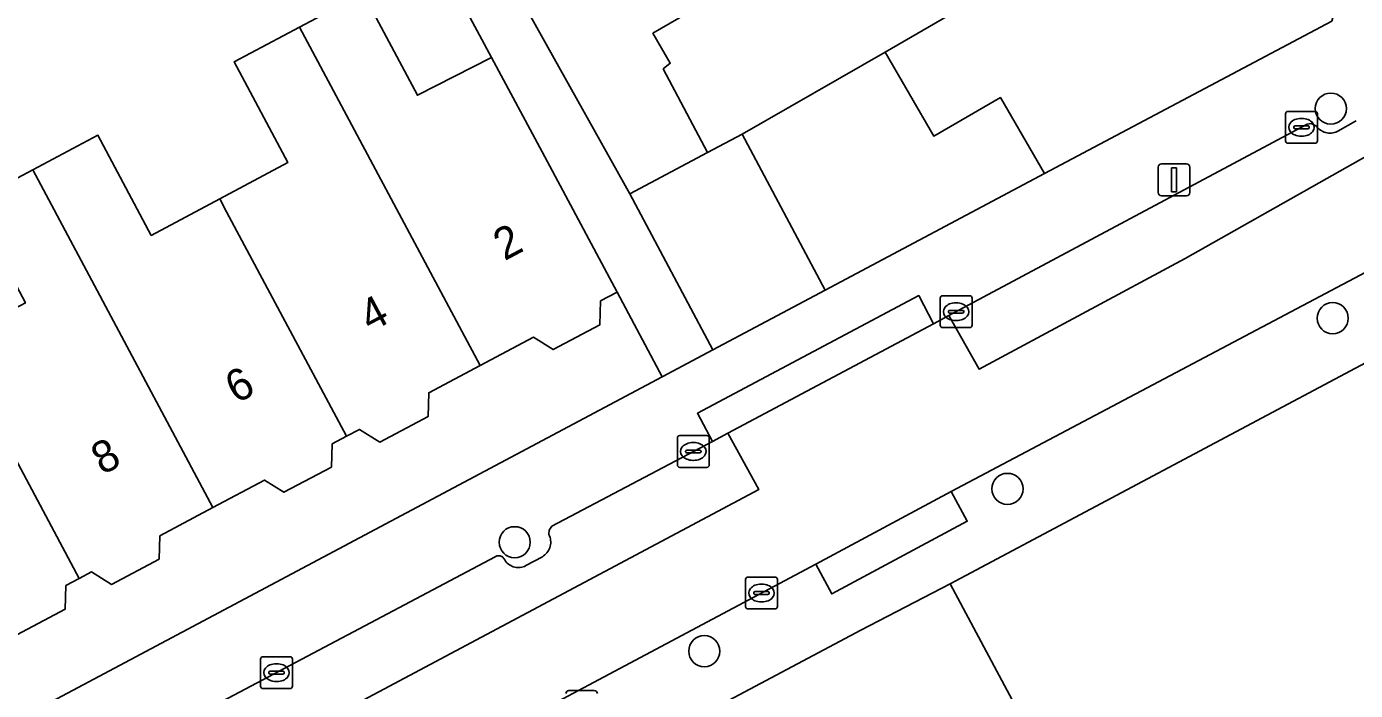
# Model space of a CAD drawing. Extents: x 160304 to 160955, y 383684 to 384161.
# Drawn here: x 160717.68 to 160759.4, y 383943.28 to 383964.14 of the extents above; entities that cross this region are included whole.
import ezdxf

# ---------------------------------------------------------------- set-up
doc = ezdxf.new("R2010")
doc.units = 0
for name, color, linetype in [('IMGEO_Boom', 7, 'Continuous'), ('IMGEO_Erf', 7, 'Continuous'), ('IMGEO_Kolk', 7, 'Continuous'), ('IMGEO_Lichtmast', 7, 'Continuous'), ('IMGEO_Muur', 7, 'Continuous'), ('IMGEO_Pand', 7, 'Continuous'), ('IMGEO_Pand_nummerreeks', 7, 'Continuous'), ('IMGEO_Parkeervlak_open', 7, 'Continuous'), ('IMGEO_Rijbaan_lokaal_open', 7, 'Continuous'), ('IMGEO_Voetpad_open', 7, 'Continuous')]:
    doc.layers.add(name, color=color, linetype=linetype)

msp = doc.modelspace()

# ---------------------------------------------------------------- linework, layer by layer
at = {"layer": 'IMGEO_Boom'}
for centre in [(160758.629, 383961.564), (160758.689, 383954.978), (160748.476, 383949.614), (160733.003, 383947.938), (160738.956, 383944.513)]:
    msp.add_circle(centre, 0.489, dxfattribs=at)
at = {"layer": 'IMGEO_Erf'}
for points in [[(160736.798, 383976.222), (160738.684, 383977.316), (160737.689, 383979.03), (160740.352, 383980.577), (160738.846, 383983.173), (160734.749, 383980.796), (160733.069, 383983.69), (160732.736, 383983.497), (160730.765, 383986.894), (160723.262, 383982.797), (160723.802, 383981.83), (160728.293, 383973.789), (160736.616, 383958.886), (160739.062, 383960.187), (160737.667, 383962.81), (160737.889, 383962.992), (160737.344, 383963.932), (160742.852, 383967.128), (160743.413, 383966.161), (160747.485, 383968.507), (160746.079, 383970.931), (160744.693, 383973.319), (160740.047, 383970.623), (160738.585, 383973.143)], [(160742.754, 383955.863), (160749.64, 383959.525), (160748.256, 383961.913), (160746.163, 383960.699), (160744.633, 383963.338), (160740.148, 383960.764)]]:
    msp.add_lwpolyline(points, close=True, dxfattribs=at)
for points in [[(160715.957, 383958.62), (160717.868, 383959.637), (160719.915, 383960.727), (160721.589, 383957.582), (160723.741, 383958.728), (160725.879, 383959.866), (160724.193, 383963.034), (160726.249, 383964.129), (160728.244, 383965.191), (160729.95, 383961.985), (160732.277, 383963.17), (160725.597, 383975.619)], [(160678.654, 383921.738), (160737.631, 383953.138), (160736.216, 383955.795), (160735.698, 383955.519), (160735.673, 383954.765), (160734.215, 383953.99), (160733.589, 383954.381), (160731.921, 383953.493), (160730.306, 383952.634), (160730.281, 383951.889), (160728.766, 383951.083), (160728.125, 383951.484), (160727.72, 383951.268), (160727.271, 383951.029), (160727.246, 383950.301), (160725.757, 383949.509), (160725.149, 383949.889), (160723.527, 383949.025), (160721.863, 383948.139), (160721.838, 383947.407), (160720.346, 383946.613), (160719.716, 383947.006), (160719.327, 383946.799), (160718.907, 383946.575), (160718.882, 383945.833), (160717.372, 383945.03)], [(160749.029, 383942.219), (160746.679, 383946.631), (160743.868, 383945.177), (160733.256, 383939.529)]]:
    msp.add_lwpolyline(points, dxfattribs=at)
at = {"layer": 'IMGEO_Kolk'}
for p, q in [((160757.208, 383960.551), (160757.208, 383961.403)), ((160757.283, 383961.477), (160758.135, 383961.477)), ((160757.696, 383961.257), (160757.721, 383961.257)), ((160758.209, 383961.403), (160758.209, 383960.551)), ((160757.467, 383960.971), (160757.467, 383960.983)), ((160757.905, 383960.934), (160757.507, 383960.934)), ((160757.51, 383961.02), (160757.908, 383961.02)), ((160757.719, 383960.697), (160757.694, 383960.697)), ((160757.951, 383960.983), (160757.951, 383960.971)), ((160758.135, 383960.477), (160757.283, 383960.477)), ((160746.438, 383955.682), (160747.29, 383955.682)), ((160746.363, 383954.756), (160746.363, 383955.608)), ((160746.851, 383955.462), (160746.876, 383955.462)), ((160747.364, 383955.608), (160747.364, 383954.756)), ((160746.622, 383955.176), (160746.622, 383955.188)), ((160747.06, 383955.139), (160746.662, 383955.139)), ((160746.665, 383955.225), (160747.063, 383955.225)), ((160746.874, 383954.902), (160746.849, 383954.902)), ((160747.106, 383955.188), (160747.106, 383955.176)), ((160747.29, 383954.682), (160746.438, 383954.682)), ((160738.111, 383950.365), (160738.111, 383951.217)), ((160738.186, 383951.291), (160739.038, 383951.291)), ((160738.599, 383951.071), (160738.624, 383951.071)), ((160739.112, 383951.217), (160739.112, 383950.365)), ((160738.37, 383950.785), (160738.37, 383950.797)), ((160738.808, 383950.748), (160738.41, 383950.748)), ((160738.413, 383950.834), (160738.811, 383950.834)), ((160738.854, 383950.797), (160738.854, 383950.785)), ((160739.038, 383950.291), (160738.186, 383950.291)), ((160738.622, 383950.511), (160738.597, 383950.511)), ((160740.253, 383945.916), (160740.253, 383946.768)), ((160740.328, 383946.842), (160741.18, 383946.842)), ((160740.741, 383946.622), (160740.766, 383946.622)), ((160741.254, 383946.768), (160741.254, 383945.916)), ((160740.512, 383946.336), (160740.512, 383946.348)), ((160740.95, 383946.299), (160740.552, 383946.299)), ((160740.555, 383946.385), (160740.953, 383946.385)), ((160740.996, 383946.348), (160740.996, 383946.336)), ((160741.18, 383945.842), (160740.328, 383945.842)), ((160740.764, 383946.062), (160740.739, 383946.062)), ((160725.023, 383943.414), (160725.023, 383944.266)), ((160725.098, 383944.34), (160725.95, 383944.34)), ((160725.511, 383944.12), (160725.536, 383944.12)), ((160726.024, 383944.266), (160726.024, 383943.414)), ((160725.282, 383943.834), (160725.282, 383943.846)), ((160725.72, 383943.797), (160725.322, 383943.797)), ((160725.325, 383943.883), (160725.723, 383943.883)), ((160725.534, 383943.56), (160725.509, 383943.56)), ((160725.766, 383943.846), (160725.766, 383943.834)), ((160725.95, 383943.34), (160725.098, 383943.34))]:
    msp.add_line(p, q, dxfattribs=at)
for points in [[(160757.208, 383960.551), (160757.208, 383961.403)], [(160757.283, 383961.477), (160758.135, 383961.477)], [(160758.209, 383961.403), (160758.209, 383960.551)], [(160758.135, 383960.477), (160757.283, 383960.477)], [(160746.438, 383955.682), (160747.29, 383955.682)], [(160746.363, 383954.756), (160746.363, 383955.608)], [(160747.364, 383955.608), (160747.364, 383954.756)], [(160747.29, 383954.682), (160746.438, 383954.682)], [(160738.111, 383950.365), (160738.111, 383951.217)], [(160738.186, 383951.291), (160739.038, 383951.291)], [(160739.112, 383951.217), (160739.112, 383950.365)], [(160739.038, 383950.291), (160738.186, 383950.291)], [(160740.253, 383945.916), (160740.253, 383946.768)], [(160740.328, 383946.842), (160741.18, 383946.842)], [(160741.254, 383946.768), (160741.254, 383945.916)], [(160741.18, 383945.842), (160740.328, 383945.842)], [(160725.023, 383943.414), (160725.023, 383944.266)], [(160725.098, 383944.34), (160725.95, 383944.34)], [(160726.024, 383944.266), (160726.024, 383943.414)], [(160725.95, 383943.34), (160725.098, 383943.34)]]:
    msp.add_lwpolyline(points, dxfattribs=at)
for centre, radius, start, end in [((160757.285, 383961.401), 0.0765, 91.552, 178.448), ((160757.285, 383961.401), 0.0765, 91.552, 178.448), ((160758.133, 383961.401), 0.0765, 1.552, 88.448), ((160758.133, 383961.401), 0.0765, 1.552, 88.448), ((160757.507, 383960.98), 0.0403, 85.8775, 175.7526), ((160757.504, 383960.97), 0.0366, 178.938, 274.7102), ((160757.908, 383960.977), 0.043, 264.8664, 352.4533), ((160757.912, 383960.982), 0.0386, 1.7309, 96.639), ((160757.285, 383960.553), 0.0765, 181.552, 268.448), ((160757.285, 383960.553), 0.0765, 181.552, 268.448), ((160758.133, 383960.553), 0.0765, 271.552, 358.448), ((160758.133, 383960.553), 0.0765, 271.552, 358.448), ((160746.44, 383955.606), 0.0765, 91.552, 178.448), ((160746.44, 383955.606), 0.0765, 91.552, 178.448), ((160747.288, 383955.606), 0.0765, 1.552, 88.448), ((160747.288, 383955.606), 0.0765, 1.552, 88.448), ((160746.662, 383955.185), 0.0403, 85.8775, 175.7526), ((160746.659, 383955.175), 0.0366, 178.938, 274.7102), ((160747.063, 383955.182), 0.043, 264.8664, 352.4533), ((160747.067, 383955.187), 0.0386, 1.7309, 96.639), ((160746.44, 383954.758), 0.0765, 181.552, 268.448), ((160746.44, 383954.758), 0.0765, 181.552, 268.448), ((160747.288, 383954.758), 0.0765, 271.552, 358.448), ((160747.288, 383954.758), 0.0765, 271.552, 358.448), ((160738.188, 383951.215), 0.0765, 91.552, 178.448), ((160738.188, 383951.215), 0.0765, 91.552, 178.448), ((160739.036, 383951.215), 0.0765, 1.552, 88.448), ((160739.036, 383951.215), 0.0765, 1.552, 88.448), ((160738.41, 383950.794), 0.0403, 85.8775, 175.7526), ((160738.407, 383950.784), 0.0366, 178.938, 274.7102), ((160738.811, 383950.791), 0.043, 264.8664, 352.4533), ((160738.815, 383950.796), 0.0386, 1.7309, 96.639), ((160738.188, 383950.367), 0.0765, 181.552, 268.448), ((160738.188, 383950.367), 0.0765, 181.552, 268.448), ((160739.036, 383950.367), 0.0765, 271.552, 358.448), ((160739.036, 383950.367), 0.0765, 271.552, 358.448), ((160740.33, 383946.766), 0.0765, 91.552, 178.448), ((160740.33, 383946.766), 0.0765, 91.552, 178.448), ((160741.178, 383946.766), 0.0765, 1.552, 88.448), ((160741.178, 383946.766), 0.0765, 1.552, 88.448), ((160740.552, 383946.345), 0.0403, 85.8775, 175.7526), ((160740.549, 383946.335), 0.0366, 178.938, 274.7102), ((160740.953, 383946.342), 0.043, 264.8664, 352.4533), ((160740.957, 383946.347), 0.0386, 1.7309, 96.639), ((160740.33, 383945.918), 0.0765, 181.552, 268.448), ((160740.33, 383945.918), 0.0765, 181.552, 268.448), ((160741.178, 383945.918), 0.0765, 271.552, 358.448), ((160741.178, 383945.918), 0.0765, 271.552, 358.448), ((160725.1, 383944.264), 0.0765, 91.552, 178.448), ((160725.1, 383944.264), 0.0765, 91.552, 178.448), ((160725.948, 383944.264), 0.0765, 1.552, 88.448), ((160725.948, 383944.264), 0.0765, 1.552, 88.448), ((160725.322, 383943.843), 0.0403, 85.8775, 175.7526), ((160725.319, 383943.833), 0.0366, 178.938, 274.7102), ((160725.723, 383943.84), 0.043, 264.8664, 352.4533), ((160725.727, 383943.845), 0.0386, 1.7309, 96.639), ((160725.1, 383943.416), 0.0765, 181.552, 268.448), ((160725.1, 383943.416), 0.0765, 181.552, 268.448), ((160725.948, 383943.416), 0.0765, 271.552, 358.448), ((160725.948, 383943.416), 0.0765, 271.552, 358.448)]:
    msp.add_arc(centre, radius, start, end, dxfattribs=at)
for centre, major_axis, ratio, start_param, end_param in [((160757.695, 383960.977), (-0.387, 0.002), 0.722429, 4.712389, 7.853982), ((160757.72, 383960.977), (-0.39, 0.002), 0.717154, 1.570796, 4.712389), ((160746.85, 383955.182), (-0.387, 0.002), 0.722429, 4.712389, 7.853982), ((160746.875, 383955.182), (-0.39, 0.002), 0.717154, 1.570796, 4.712389), ((160738.598, 383950.791), (-0.387, 0.002), 0.722429, 4.712389, 7.853982), ((160738.623, 383950.791), (-0.39, 0.002), 0.717154, 1.570796, 4.712389), ((160740.74, 383946.342), (-0.387, 0.002), 0.722429, 4.712389, 7.853982), ((160740.765, 383946.342), (-0.39, 0.002), 0.717154, 1.570796, 4.712389), ((160725.51, 383943.84), (-0.387, 0.002), 0.722429, 4.712389, 7.853982), ((160725.535, 383943.84), (-0.39, 0.002), 0.717154, 1.570796, 4.712389)]:
    msp.add_ellipse(centre, major_axis=major_axis, ratio=ratio, start_param=start_param, end_param=end_param, dxfattribs=at)
at = {"layer": 'IMGEO_Lichtmast'}
for p, q in [((160753.212, 383958.925), (160753.212, 383959.725)), ((160753.212, 383959.725), (160753.212, 383958.925)), ((160753.312, 383959.825), (160754.102, 383959.825)), ((160754.102, 383959.825), (160753.312, 383959.825)), ((160754.202, 383959.725), (160754.202, 383958.925)), ((160754.202, 383958.925), (160754.202, 383959.725)), ((160754.102, 383958.825), (160753.312, 383958.825)), ((160753.312, 383958.825), (160754.102, 383958.825)), ((160734.708, 383943.281), (160735.498, 383943.281)), ((160735.498, 383943.281), (160734.708, 383943.281))]:
    msp.add_line(p, q, dxfattribs=at)
msp.add_lwpolyline([(160753.632, 383959.7), (160753.782, 383959.7), (160753.782, 383958.95), (160753.632, 383958.95), (160753.632, 383959.7)], dxfattribs=at)
for centre, start, end in [((160753.312, 383959.725), 90, 180), ((160753.312, 383959.725), 90, 180), ((160754.102, 383959.725), 0, 90), ((160754.102, 383959.725), 360, 90), ((160753.312, 383958.925), 180, 270), ((160753.312, 383958.925), 180, 270), ((160754.102, 383958.925), 270, 0), ((160754.102, 383958.925), 270, 0), ((160734.708, 383943.181), 90, 180), ((160734.708, 383943.181), 90, 180), ((160735.498, 383943.181), 0, 90), ((160735.498, 383943.181), 360, 90)]:
    msp.add_arc(centre, 0.1, start, end, dxfattribs=at)
at = {"layer": 'IMGEO_Muur'}
msp.add_lwpolyline([(160742.754, 383955.863), (160749.64, 383959.525)], dxfattribs=at)
at = {"layer": 'IMGEO_Pand'}
for points in [[(160756.62, 383970.294), (160753.688, 383975.347), (160746.079, 383970.931), (160747.485, 383968.507), (160743.413, 383966.161), (160742.852, 383967.128), (160737.344, 383963.932), (160737.889, 383962.992), (160737.667, 383962.81), (160739.062, 383960.187), (160740.148, 383960.764), (160744.633, 383963.338)], [(160744.633, 383963.338), (160746.163, 383960.699), (160748.256, 383961.913), (160749.64, 383959.525), (160758.663, 383964.313), (160759.111, 383966), (160756.62, 383970.294)], [(160731.921, 383953.493), (160733.589, 383954.381), (160734.215, 383953.99), (160735.673, 383954.765), (160735.698, 383955.519), (160736.216, 383955.795), (160733.866, 383960.209), (160732.277, 383963.17), (160729.95, 383961.985), (160728.244, 383965.191), (160726.249, 383964.129)], [(160723.741, 383958.728), (160723.956, 383958.324), (160727.72, 383951.268), (160728.125, 383951.484), (160728.766, 383951.083), (160730.281, 383951.889), (160730.306, 383952.634), (160731.921, 383953.493), (160726.249, 383964.129), (160724.193, 383963.034), (160725.879, 383959.866)], [(160723.741, 383958.728), (160721.589, 383957.582), (160719.915, 383960.727), (160717.868, 383959.637), (160723.527, 383949.025), (160725.149, 383949.889), (160725.757, 383949.509), (160727.246, 383950.301), (160727.271, 383951.029), (160727.72, 383951.268), (160723.956, 383958.324)], [(160739.062, 383960.187), (160736.616, 383958.886), (160739.222, 383953.985), (160742.754, 383955.863), (160740.148, 383960.764)], [(160717.868, 383959.637), (160715.957, 383958.62), (160717.641, 383955.457), (160715.438, 383954.285), (160715.358, 383954.242), (160715.565, 383953.853), (160719.327, 383946.799), (160719.716, 383947.006), (160720.346, 383946.613), (160721.838, 383947.407), (160721.863, 383948.139), (160723.527, 383949.025)], [(160715.565, 383953.853), (160715.358, 383954.242), (160715.438, 383954.285), (160713.865, 383957.24), (160711.587, 383956.027), (160711.493, 383956.203), (160709.491, 383955.137), (160715.148, 383944.531), (160716.779, 383945.399), (160717.372, 383945.03), (160718.882, 383945.833), (160718.907, 383946.575), (160719.327, 383946.799)]]:
    msp.add_lwpolyline(points, close=True, dxfattribs=at)
msp.add_lwpolyline([(160763.561, 383921.679), (160764.905, 383922.4), (160764.211, 383923.733), (160762.632, 383926.766), (160762.836, 383926.872), (160755.313, 383941.326), (160758.181, 383942.852), (160759.15, 383941.031), (160758.853, 383940.873), (160763.562, 383929.215), (160763.412, 383929.155), (160764.632, 383926.135), (160764.868, 383926.23), (160766.091, 383923.202), (160766.146, 383923.065), (160775.576, 383928.118), (160764.306, 383956.019), (160746.679, 383946.631), (160749.029, 383942.219), (160750.548, 383939.37), (160747.723, 383937.882), (160757.123, 383920.035)], dxfattribs=at)
at = {"layer": 'IMGEO_Parkeervlak_open'}
for points in [[(160759.431, 383961.181), (160759.401, 383961.169), (160758.85, 383960.858), (160758.825, 383960.845), (160758.783, 383960.826), (160758.74, 383960.812), (160758.695, 383960.801), (160758.65, 383960.795), (160758.605, 383960.792), (160758.559, 383960.794), (160758.514, 383960.8), (160758.469, 383960.809), (160758.426, 383960.823), (160758.384, 383960.841), (160758.343, 383960.862), (160758.305, 383960.886), (160758.269, 383960.914), (160758.236, 383960.945), (160758.205, 383960.979), (160758.178, 383961.016), (160758.014, 383961.093), (160757.887, 383961.071), (160746.638, 383955.061), (160747.583, 383953.379), (160754.061, 383956.857), (160761.345, 383960.972)], [(160723.902, 383940.663), (160740.664, 383949.591), (160739.696, 383951.366), (160739.21, 383951.107), (160734.168, 383948.439), (160734.087, 383948.315), (160734.071, 383948.191), (160734.077, 383948.179), (160734.097, 383948.136), (160734.112, 383948.092), (160734.124, 383948.046), (160734.131, 383948), (160734.135, 383947.953), (160734.134, 383947.906), (160734.129, 383947.859), (160734.119, 383947.813), (160734.106, 383947.767), (160734.089, 383947.724), (160734.067, 383947.682), (160734.043, 383947.642), (160734.014, 383947.604), (160733.983, 383947.569), (160733.948, 383947.537), (160733.911, 383947.508), (160733.871, 383947.483), (160733.352, 383947.202), (160733.307, 383947.18), (160733.265, 383947.165), (160733.222, 383947.154), (160733.179, 383947.146), (160733.134, 383947.142), (160733.09, 383947.142), (160733.046, 383947.147), (160733.002, 383947.155), (160732.959, 383947.167), (160732.918, 383947.183), (160732.878, 383947.202), (160732.84, 383947.225), (160732.804, 383947.251), (160732.771, 383947.281), (160732.74, 383947.313), (160732.712, 383947.348), (160732.688, 383947.385), (160732.667, 383947.424), (160732.656, 383947.439), (160732.644, 383947.452), (160732.631, 383947.465), (160732.616, 383947.476), (160732.601, 383947.486), (160732.585, 383947.494), (160732.568, 383947.501), (160732.55, 383947.507), (160732.532, 383947.511), (160732.514, 383947.513), (160732.496, 383947.514), (160732.478, 383947.513), (160732.46, 383947.51), (160732.442, 383947.506), (160732.424, 383947.5), (160732.408, 383947.493), (160732.385, 383947.48), (160722.941, 383942.467)]]:
    msp.add_lwpolyline(points, dxfattribs=at)
at = {"layer": 'IMGEO_Rijbaan_lokaal_open'}
msp.add_lwpolyline([(160763.531, 383958.431), (160762.277, 383960.65), (160761.073, 383962.781), (160760.503, 383962.462), (160761.345, 383960.972), (160754.061, 383956.857), (160747.583, 383953.379), (160746.638, 383955.061), (160746.158, 383954.804), (160739.696, 383951.366), (160740.664, 383949.591), (160723.902, 383940.663), (160725.268, 383938.098), (160742.456, 383947.25), (160746.712, 383949.534)], close=True, dxfattribs=at)
at = {"layer": 'IMGEO_Voetpad_open'}
for points in [[(160725.597, 383975.619), (160732.277, 383963.17), (160733.866, 383960.209), (160736.216, 383955.795), (160737.631, 383953.138), (160739.222, 383953.985), (160736.616, 383958.886), (160728.293, 383973.789)], [(160758.663, 383964.313), (160749.64, 383959.525), (160742.754, 383955.863), (160739.222, 383953.985), (160737.631, 383953.138), (160678.654, 383921.738)], [(160722.941, 383942.467), (160732.385, 383947.48), (160732.408, 383947.493), (160732.424, 383947.5), (160732.442, 383947.506), (160732.46, 383947.51), (160732.478, 383947.513), (160732.496, 383947.514), (160732.514, 383947.513), (160732.532, 383947.511), (160732.55, 383947.507), (160732.568, 383947.501), (160732.585, 383947.494), (160732.601, 383947.486), (160732.616, 383947.476), (160732.631, 383947.465), (160732.644, 383947.452), (160732.656, 383947.439), (160732.667, 383947.424), (160732.688, 383947.385), (160732.712, 383947.348), (160732.74, 383947.313), (160732.771, 383947.281), (160732.804, 383947.251), (160732.84, 383947.225), (160732.878, 383947.202), (160732.918, 383947.183), (160732.959, 383947.167), (160733.002, 383947.155), (160733.046, 383947.147), (160733.09, 383947.142), (160733.134, 383947.142), (160733.179, 383947.146), (160733.222, 383947.154), (160733.265, 383947.165), (160733.307, 383947.18), (160733.352, 383947.202), (160733.871, 383947.483), (160733.911, 383947.508), (160733.948, 383947.537), (160733.983, 383947.569), (160734.014, 383947.604), (160734.043, 383947.642), (160734.067, 383947.682), (160734.089, 383947.724), (160734.106, 383947.767), (160734.119, 383947.813), (160734.129, 383947.859), (160734.134, 383947.906), (160734.135, 383947.953), (160734.131, 383948), (160734.124, 383948.046), (160734.112, 383948.092), (160734.097, 383948.136), (160734.077, 383948.179), (160734.071, 383948.191), (160734.087, 383948.315), (160734.168, 383948.439), (160739.21, 383951.107), (160738.741, 383951.99), (160745.689, 383955.687), (160746.158, 383954.804), (160746.638, 383955.061), (160757.887, 383961.071), (160758.014, 383961.093), (160758.178, 383961.016), (160758.205, 383960.979), (160758.236, 383960.945), (160758.269, 383960.914), (160758.305, 383960.886), (160758.343, 383960.862), (160758.384, 383960.841), (160758.426, 383960.823), (160758.469, 383960.809), (160758.514, 383960.8), (160758.559, 383960.794), (160758.605, 383960.792), (160758.65, 383960.795), (160758.695, 383960.801), (160758.74, 383960.812), (160758.783, 383960.826), (160758.825, 383960.845), (160758.85, 383960.858), (160759.401, 383961.169), (160759.431, 383961.181)]]:
    msp.add_lwpolyline(points, dxfattribs=at)
for points in [[(160731.321, 383938.411), (160731.813, 383938.673), (160732.617, 383939.108), (160733.152, 383939.46), (160733.256, 383939.529), (160743.868, 383945.177), (160746.679, 383946.631), (160764.306, 383956.019), (160763.531, 383958.431), (160746.712, 383949.534), (160747.214, 383948.6), (160742.958, 383946.316), (160742.456, 383947.25), (160725.268, 383938.098), (160722.832, 383936.801), (160682.288, 383915.213), (160683.374, 383912.887)], [(160746.158, 383954.804), (160745.689, 383955.687), (160738.741, 383951.99), (160739.21, 383951.107), (160739.696, 383951.366)], [(160742.456, 383947.25), (160742.958, 383946.316), (160747.214, 383948.6), (160746.712, 383949.534)]]:
    msp.add_lwpolyline(points, close=True, dxfattribs=at)

# ---------------------------------------------------------------- texts
at = {"layer": 'IMGEO_Pand_nummerreeks'}
for s, rotation, p in [('2', 28.0578, (160732.681, 383956.766)), ('4', 28.0578, (160728.472, 383954.523)), ('6', 28.0578, (160724.261, 383952.278)), ('8', 28.0577, (160720.054, 383950.036))]:
    msp.add_text(s, height=1, rotation=rotation, dxfattribs=at).set_placement(p)

doc.saveas('drawing.dxf')
